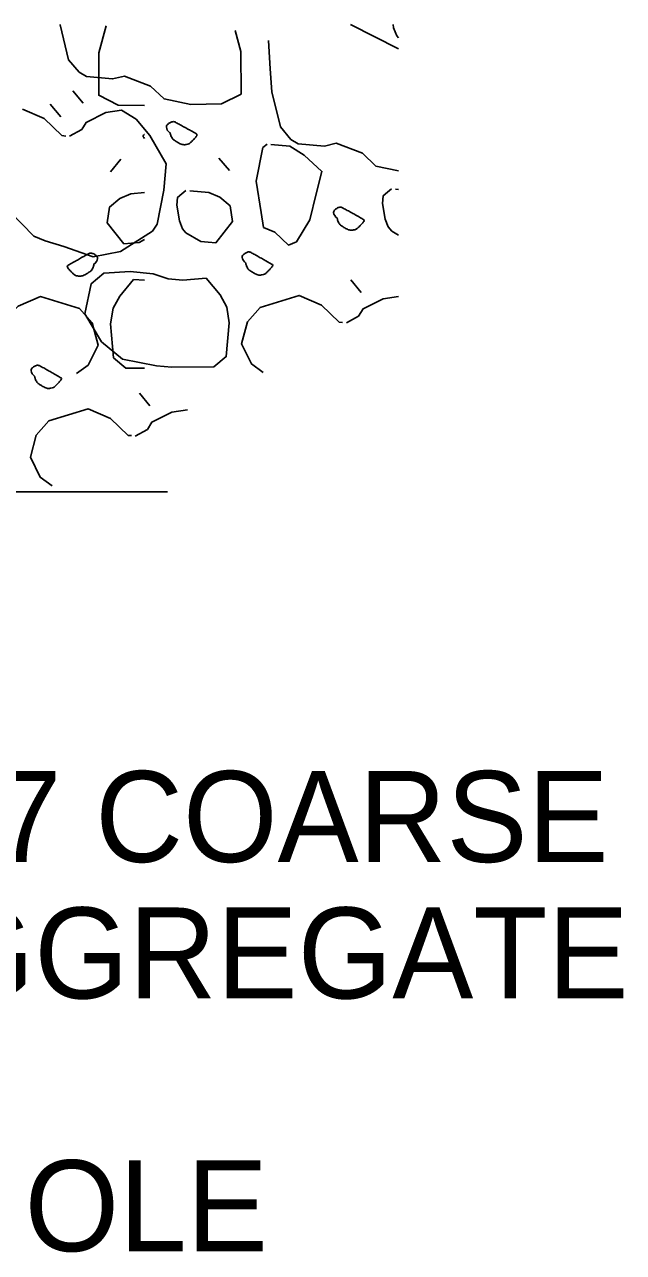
# Model space of a CAD drawing. Extents: x 1299104.8 to 1299141.6, y 239639.8 to 239661.8.
# Drawn here: x 1299129.628 to 1299130.419, y 239645.94 to 239647.559 of the extents above; entities that cross this region are included whole.
import ezdxf

# ---------------------------------------------------------------- set-up
doc = ezdxf.new("R2010")
doc.units = 0
doc.layers.add('DIM TXT', color=7, linetype='Continuous')

msp = doc.modelspace()

# ---------------------------------------------------------------- linework, layer by layer
at = {"layer": 'DIM TXT'}
for p, q in [((1299130.0583, 239647.5594), (1299130.1217, 239647.5276)), ((1299129.6917, 239647.472), (1299129.7055, 239647.4555)), ((1299129.6621, 239647.4543), (1299129.676, 239647.4377)), ((1299129.7553, 239647.3818), (1299129.7414, 239647.3653)), ((1299129.8846, 239647.3833), (1299129.8985, 239647.3668)), ((1299130.1176, 239647.3424), (1299130.1217, 239647.342)), ((1299130.0586, 239647.2227), (1299130.0724, 239647.2061)), ((1299129.7798, 239647.0732), (1299129.7937, 239647.0566)), ((1299128.9903, 239646.9431), (1299129.8166, 239646.9431)), ((1299129.0633, 239646.9431), (1299129.8166, 239646.9431))]:
    msp.add_line(p, q, dxfattribs=at)
for points in [[(1299129.9063, 239647.5517), (1299129.9138, 239647.5237), (1299129.914, 239647.4677), (1299129.8882, 239647.4547), (1299129.8474, 239647.454), (1299129.8124, 239647.4613), (1299129.7944, 239647.4782), (1299129.7599, 239647.4913), (1299129.7444, 239647.4877), (1299129.7097, 239647.4907), (1299129.7001, 239647.4967), (1299129.6862, 239647.5131), (1299129.675, 239647.5591), (1299129.675, 239647.5594)], [(1299129.7357, 239647.5579), (1299129.7261, 239647.5222), (1299129.726, 239647.4662), (1299129.7518, 239647.4532), (1299129.7863, 239647.4526)], [(1299130.1217, 239647.5417), (1299130.1196, 239647.5447), (1299130.1153, 239647.5553), (1299130.1147, 239647.5594)], [(1299130.1217, 239647.3664), (1299130.092, 239647.3728), (1299130.074, 239647.3896), (1299130.0395, 239647.4028), (1299130.024, 239647.3991), (1299129.9893, 239647.4021), (1299129.9797, 239647.408), (1299129.9658, 239647.4244), (1299129.9546, 239647.4705), (1299129.9522, 239647.5012), (1299129.9502, 239647.5383)], [(1299129.6876, 239647.412), (1299129.7036, 239647.4208), (1299129.7096, 239647.4304), (1299129.7353, 239647.4435), (1299129.756, 239647.4467), (1299129.7753, 239647.4348), (1299129.7937, 239647.4129), (1299129.8151, 239647.3755), (1299129.8121, 239647.3408), (1299129.8031, 239647.2959), (1299129.7972, 239647.2869), (1299129.7549, 239647.2601), (1299129.7187, 239647.2531), (1299129.68, 239647.2667), (1299129.6552, 239647.2739), (1299129.6405, 239647.2803), (1299129.6085, 239647.3129)], [(1299129.6253, 239647.4479), (1299129.6541, 239647.4353), (1299129.6775, 239647.4129), (1299129.6825, 239647.4124)], [(1299129.9532, 239647.4013), (1299129.9785, 239647.3992), (1299129.997, 239647.3873), (1299130.0206, 239647.3657), (1299130.0129, 239647.3359), (1299130.0048, 239647.3017), (1299129.987, 239647.2727), (1299129.9765, 239647.2685), (1299129.9584, 239647.2854), (1299129.9436, 239647.2918), (1299129.9404, 239647.3117), (1299129.9338, 239647.3529), (1299129.9428, 239647.3972), (1299129.9482, 239647.4018)], [(1299129.7863, 239647.3379), (1299129.7686, 239647.3363), (1299129.754, 239647.3299), (1299129.7404, 239647.3186), (1299129.7371, 239647.2979), (1299129.7592, 239647.2701), (1299129.7693, 239647.271), (1299129.7794, 239647.2719), (1299129.7863, 239647.2758)], [(1299129.8461, 239647.3401), (1299129.8713, 239647.3379), (1299129.886, 239647.3315), (1299129.8996, 239647.3201), (1299129.9028, 239647.2995), (1299129.8808, 239647.2716), (1299129.8706, 239647.2725), (1299129.8606, 239647.2734), (1299129.8412, 239647.2845), (1299129.8366, 239647.2901), (1299129.8325, 239647.3005), (1299129.8292, 239647.3212), (1299129.8301, 239647.3313), (1299129.8356, 239647.3359), (1299129.841, 239647.3405)], [(1299130.1217, 239647.2817), (1299130.1128, 239647.2869), (1299130.1081, 239647.2924), (1299130.104, 239647.3029), (1299130.1007, 239647.3235), (1299130.1016, 239647.3336), (1299130.107, 239647.3382), (1299130.1125, 239647.3428)], [(1299129.8372, 239647.2224), (1299129.8678, 239647.2247), (1299129.8862, 239647.2028), (1299129.895, 239647.1867), (1299129.8982, 239647.1661), (1299129.8944, 239647.1215), (1299129.878, 239647.1077), (1299129.8226, 239647.1073), (1299129.8025, 239647.1091), (1299129.7576, 239647.1182), (1299129.7297, 239647.1409), (1299129.7076, 239647.1777), (1299129.7161, 239647.2176), (1299129.7326, 239647.2315), (1299129.7676, 239647.2335), (1299129.7978, 239647.2308), (1299129.8176, 239647.2241), (1299129.8372, 239647.2224)], [(1299129.7863, 239647.2221), (1299129.7721, 239647.2232), (1299129.7537, 239647.2013), (1299129.7449, 239647.1852), (1299129.7417, 239647.1646), (1299129.7456, 239647.1199), (1299129.762, 239647.1061), (1299129.7863, 239647.106)], [(1299129.6967, 239647.0989), (1299129.7123, 239647.1102), (1299129.7252, 239647.1367), (1299129.7176, 239647.1659), (1299129.7008, 239647.1847), (1299129.6492, 239647.2005), (1299129.6198, 239647.1878), (1299129.5964, 239647.1654), (1299129.5921, 239647.1651)], [(1299129.9432, 239647.1004), (1299129.9276, 239647.1117), (1299129.9147, 239647.1383), (1299129.9223, 239647.1674), (1299129.9392, 239647.1863), (1299129.9907, 239647.2021), (1299130.0201, 239647.1893), (1299130.0436, 239647.1669), (1299130.0478, 239647.1666)], [(1299130.053, 239647.1661), (1299130.069, 239647.1749), (1299130.0749, 239647.1845), (1299130.1014, 239647.1975), (1299130.1217, 239647.2007)], [(1299129.6645, 239646.951), (1299129.6489, 239646.9622), (1299129.636, 239646.9888), (1299129.6436, 239647.0179), (1299129.6604, 239647.0368), (1299129.712, 239647.0526), (1299129.7414, 239647.0398), (1299129.7648, 239647.0174), (1299129.7691, 239647.0171)], [(1299129.7742, 239647.0166), (1299129.7902, 239647.0254), (1299129.7962, 239647.035), (1299129.8227, 239647.048), (1299129.843, 239647.0512)]]:
    msp.add_lwpolyline(points, dxfattribs=at)
for points in [[(1299129.8202, 239647.4171), (1299129.8206, 239647.4147), (1299129.8213, 239647.4125), (1299129.8226, 239647.4104), (1299129.8239, 239647.4082), (1299129.8258, 239647.4069), (1299129.828, 239647.4055), (1299129.8324, 239647.4026), (1299129.8376, 239647.4005), (1299129.8421, 239647.4013), (1299129.8452, 239647.4019), (1299129.8479, 239647.4044), (1299129.8506, 239647.4072), (1299129.853, 239647.4096), (1299129.8568, 239647.414), (1299129.8542, 239647.4156), (1299129.8513, 239647.4174), (1299129.8482, 239647.419), (1299129.8452, 239647.4207), (1299129.8394, 239647.4239), (1299129.8337, 239647.4271), (1299129.8279, 239647.4302), (1299129.8248, 239647.4318), (1299129.8204, 239647.4305), (1299129.8176, 239647.4283), (1299129.8143, 239647.4256), (1299129.8167, 239647.4185), (1299129.8201, 239647.4164)], [(1299129.7863, 239647.4092), (1299129.7849, 239647.4112), (1299129.7841, 239647.4131), (1299129.7859, 239647.4142), (1299129.7861, 239647.4143), (1299129.7863, 239647.4144)], [(1299130.0408, 239647.3043), (1299130.0412, 239647.3019), (1299130.0418, 239647.2997), (1299130.0431, 239647.2975), (1299130.0444, 239647.2953), (1299130.0463, 239647.294), (1299130.0484, 239647.2927), (1299130.0529, 239647.2898), (1299130.0581, 239647.2877), (1299130.0626, 239647.2885), (1299130.0658, 239647.2891), (1299130.0685, 239647.2916), (1299130.0712, 239647.2943), (1299130.0735, 239647.2967), (1299130.0773, 239647.3011), (1299130.0748, 239647.3027), (1299130.0718, 239647.3044), (1299130.0687, 239647.3061), (1299130.0657, 239647.3079), (1299130.0599, 239647.3111), (1299130.0542, 239647.3143), (1299130.0484, 239647.3174), (1299130.0454, 239647.319), (1299130.0409, 239647.3176), (1299130.0381, 239647.3153), (1299130.0348, 239647.3126), (1299130.0379, 239647.3057), (1299130.0414, 239647.3035)], [(1299129.7198, 239647.2435), (1299129.7194, 239647.2412), (1299129.7188, 239647.239), (1299129.7175, 239647.2368), (1299129.7162, 239647.2346), (1299129.7143, 239647.2333), (1299129.7121, 239647.2319), (1299129.7076, 239647.2291), (1299129.7025, 239647.227), (1299129.698, 239647.2278), (1299129.6948, 239647.2284), (1299129.6921, 239647.2309), (1299129.6894, 239647.2337), (1299129.6871, 239647.2361), (1299129.6832, 239647.2405), (1299129.6858, 239647.242), (1299129.6888, 239647.2437), (1299129.6919, 239647.2454), (1299129.6949, 239647.2471), (1299129.7006, 239647.2504), (1299129.7064, 239647.2536), (1299129.7121, 239647.2567), (1299129.7152, 239647.2584), (1299129.7197, 239647.257), (1299129.7225, 239647.2547), (1299129.7257, 239647.2519), (1299129.7226, 239647.245), (1299129.7192, 239647.2427)], [(1299129.9201, 239647.2451), (1299129.9205, 239647.2427), (1299129.9212, 239647.2405), (1299129.9224, 239647.2383), (1299129.9237, 239647.2361), (1299129.9256, 239647.2349), (1299129.9278, 239647.2335), (1299129.9323, 239647.2306), (1299129.9375, 239647.2285), (1299129.942, 239647.2293), (1299129.9451, 239647.2299), (1299129.9478, 239647.2324), (1299129.9505, 239647.2352), (1299129.9529, 239647.2376), (1299129.9567, 239647.242), (1299129.9541, 239647.2435), (1299129.9511, 239647.2453), (1299129.9481, 239647.247), (1299129.945, 239647.2487), (1299129.9393, 239647.2519), (1299129.9336, 239647.2551), (1299129.9278, 239647.2583), (1299129.9247, 239647.26), (1299129.9202, 239647.2585), (1299129.9174, 239647.2562), (1299129.9142, 239647.2535), (1299129.9173, 239647.2466), (1299129.9208, 239647.2443)], [(1299129.6414, 239647.0956), (1299129.6418, 239647.0932), (1299129.6424, 239647.091), (1299129.6437, 239647.0888), (1299129.645, 239647.0866), (1299129.6469, 239647.0854), (1299129.6491, 239647.084), (1299129.6535, 239647.0812), (1299129.6587, 239647.079), (1299129.6632, 239647.0798), (1299129.6664, 239647.0804), (1299129.6691, 239647.0829), (1299129.6718, 239647.0857), (1299129.6741, 239647.0881), (1299129.678, 239647.0925), (1299129.6754, 239647.094), (1299129.6724, 239647.0958), (1299129.6693, 239647.0975), (1299129.6663, 239647.0992), (1299129.6606, 239647.1024), (1299129.6548, 239647.1056), (1299129.6491, 239647.1088), (1299129.646, 239647.1105), (1299129.6415, 239647.109), (1299129.6387, 239647.1067), (1299129.6355, 239647.104), (1299129.6386, 239647.0971), (1299129.642, 239647.0948)]]:
    msp.add_open_spline(points, degree=3, dxfattribs=at)

# ---------------------------------------------------------------- texts
for s, p in [('#57 COARSE', (1299129.4091, 239646.4547)), ('AGGREGATE', (1299129.4091, 239646.2747)), ('DRAIN HOLE', (1299128.9685, 239645.9413))]:
    msp.add_text(s, height=0.12, dxfattribs=at).set_placement(p)

doc.saveas('drawing.dxf')
